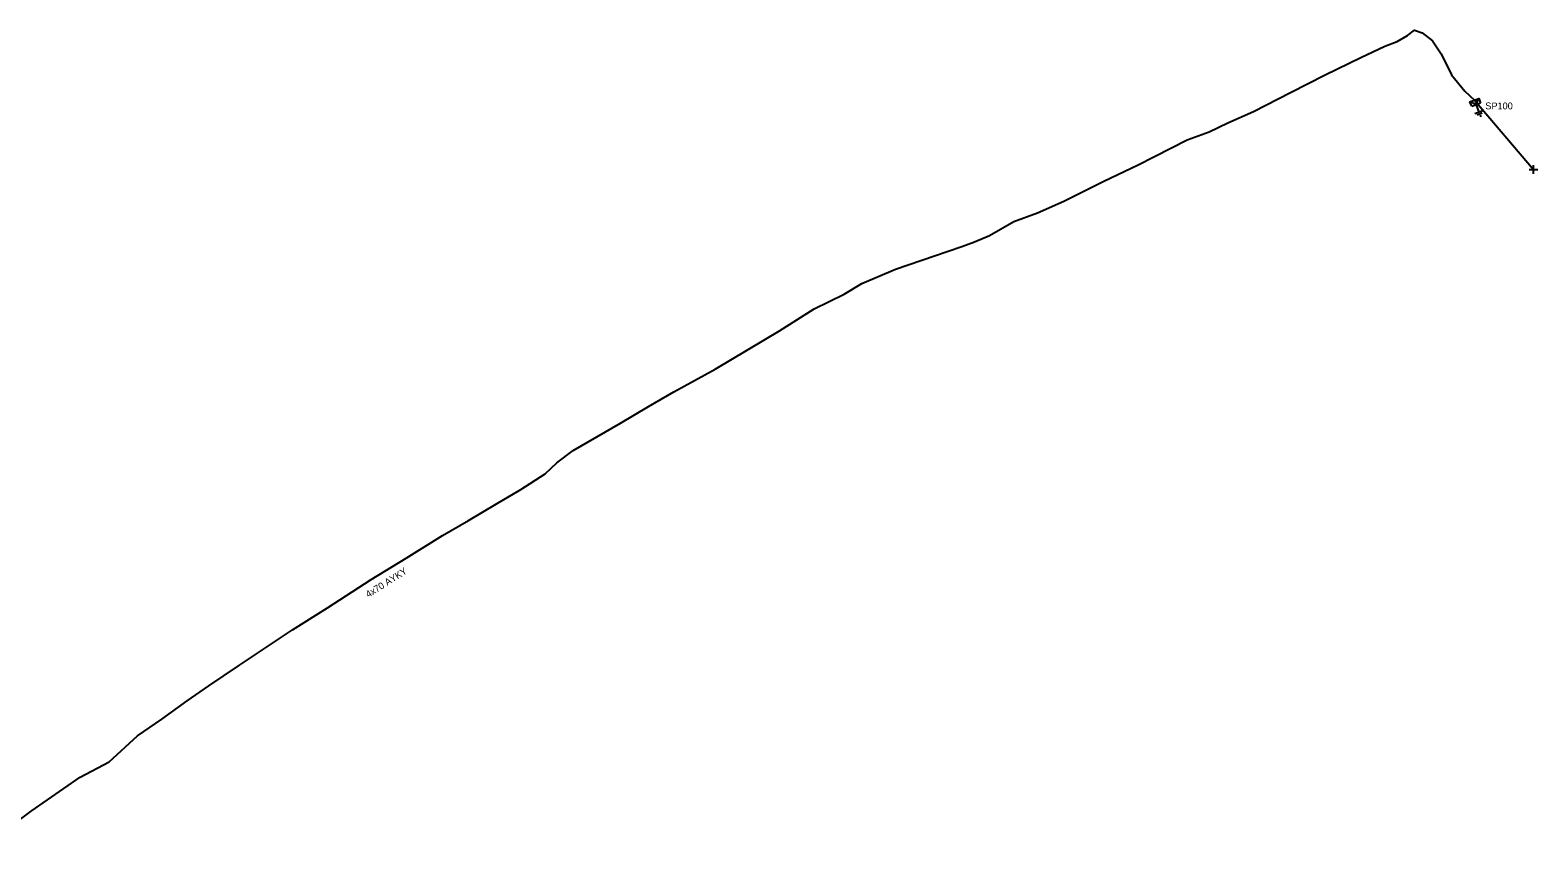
# Model space of a CAD drawing. Extents: x -763093 to -760976, y -1155572 to -1152009.
# Drawn here: x -761507.5 to -761286.9, y -1154461 to -1154341.4 of the extents above; entities that cross this region are included whole.
import ezdxf

# ---------------------------------------------------------------- set-up
doc = ezdxf.new("R2010")
doc.units = 0
for name, color, linetype in [('Vrstva 1', 7, 'Continuous'), ('Vrstva 14', 7, 'Continuous'), ('Vrstva 15', 7, 'Continuous'), ('Vrstva 31', 7, 'Continuous'), ('Vrstva 33', 7, 'Continuous'), ('Vrstva 34', 7, 'Continuous'), ('Vrstva 5', 7, 'Continuous'), ('Vrstva 59', 7, 'Continuous'), ('Vrstva 6', 7, 'Continuous'), ('Vrstva 9', 7, 'Continuous')]:
    doc.layers.add(name, color=color, linetype=linetype)

# ---------------------------------------------------------------- blocks, each defined once
blk = doc.blocks.new('NN800')
at = {"layer": 'Vrstva 1'}
for points in [[(-0.44, 0.44), (0.44, -0.44)], [(-0.44, -0.44), (0.44, 0.44)]]:
    blk.add_lwpolyline(points, dxfattribs=at)
blk = doc.blocks.new('NN630')
at = {"layer": 'Vrstva 9'}
for points in [[(0, -0.7), (-0.7, 0)], [(-0.7, -0.7), (-0.7, 0), (0.7, 0), (0.7, -0.7)], [(-0.7, -0.7), (0.7, -0.7)], [(0, -0.7), (0.7, 0)]]:
    blk.add_lwpolyline(points, dxfattribs=at)
blk = doc.blocks.new('NN810')
at = {"layer": 'Vrstva 14'}
for points in [[(0.63, -1.89), (-0.62, -1.89)], [(0.39, -2.2), (-0.4, -2.2)], [(0, -0.64), (0, -1.89)], [(0, -2.52), (-0.12, -2.52)], [(0.14, -2.52), (0, -2.52)]]:
    blk.add_lwpolyline(points, dxfattribs=at)

msp = doc.modelspace()

# ---------------------------------------------------------------- linework, layer by layer
at = {"layer": 'Vrstva 5'}
msp.add_lwpolyline([(-761514.43, -1154461.03), (-761507.38, -1154455.82), (-761500.22, -1154450.83), (-761495.99, -1154448.57), (-761491.81, -1154444.76), (-761488.27, -1154442.34), (-761484.58, -1154439.63), (-761481.39, -1154437.46), (-761477.04, -1154434.53), (-761473.24, -1154431.96), (-761469.16, -1154429.23), (-761464.03, -1154426.01), (-761457.62, -1154421.89), (-761452.53, -1154418.74), (-761447.2, -1154415.45), (-761443.39, -1154413.25), (-761439.27, -1154410.81), (-761435.74, -1154408.71), (-761432.15, -1154406.39), (-761430.46, -1154404.78), (-761428.08, -1154403), (-761424.6, -1154400.98), (-761421.13, -1154398.96), (-761417.02, -1154396.54), (-761413.32, -1154394.4), (-761407.29, -1154391.07), (-761402.43, -1154388.2), (-761397.84, -1154385.43), (-761392.78, -1154382.25), (-761388.39, -1154380.07), (-761385.8, -1154378.54), (-761380.88, -1154376.42), (-761375.18, -1154374.48), (-761371.19, -1154373.08), (-761369.3, -1154372.42), (-761367.14, -1154371.48), (-761363.54, -1154369.43), (-761360.08, -1154368.18), (-761356.23, -1154366.44), (-761350.38, -1154363.54), (-761345.35, -1154361.14), (-761338.19, -1154357.49), (-761334.99, -1154356.32), (-761332.25, -1154354.97), (-761328.49, -1154353.35), (-761323.05, -1154350.52), (-761318.01, -1154347.96), (-761312.77, -1154345.4), (-761309.28, -1154343.77), (-761307.47, -1154343.07), (-761305.94, -1154342.21), (-761304.92, -1154341.41), (-761303.81, -1154341.79), (-761302.3, -1154343), (-761301, -1154344.87), (-761299.48, -1154347.98), (-761297.53, -1154350.34), (-761296.15, -1154351.66)], dxfattribs=at)
at = {"layer": 'Vrstva 59'}
msp.add_lwpolyline([(-761296.15, -1154351.66), (-761287.49, -1154361.82)], dxfattribs=at)

# ---------------------------------------------------------------- block references
at = {"layer": 'Vrstva 15', "rotation": 20.500724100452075}
msp.add_blockref('NN810', (-761296.15, -1154351.66), dxfattribs=at)
at = {"layer": 'Vrstva 31', "rotation": 21.190350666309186}
msp.add_blockref('NN630', (-761296.15, -1154351.66), dxfattribs=at)
at = {"layer": 'Vrstva 34', "rotation": 45}
msp.add_blockref('NN800', (-761287.49, -1154361.82), dxfattribs=at)

# ---------------------------------------------------------------- texts
at = {"layer": 'Vrstva 33'}
msp.add_text('SP100', height=1, dxfattribs=at).set_placement((-761294.55, -1154353.01))
at = {"layer": 'Vrstva 6'}
msp.add_text('4x70 AYKY', height=1, rotation=32.548, dxfattribs=at).set_placement((-761458.03, -1154424.57))

doc.saveas('drawing.dxf')
